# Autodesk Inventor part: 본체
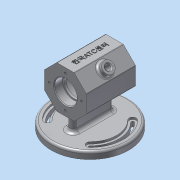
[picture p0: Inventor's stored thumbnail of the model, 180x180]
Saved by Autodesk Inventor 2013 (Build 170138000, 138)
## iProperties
Created: 2017-06
Part Number: 본체
Material: 알루미늄 6061
Document SubType Name: Modeling
Designer: Administrator
Density: 2.71 g/cm^3
Mass: 559.99 g
Surface Area: 567.595 cm^2
Volume: 206.638 cm^3
Author: Administrator
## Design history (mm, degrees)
sketch "스케치1"
  geometry: C1 r 55 at (0, 0); 1 further point
  constraints: 1 centre point, 1 coincident
  dimensions: "d0" = 110 diameter of C1
extrude "돌출1" new body sketch "스케치1" distance "d2" = 10; taper "d3" = 0 deg
sketch "스케치2"
  geometry: L1 (55, 10)-(-55, 10) reference; L2 (-55, 0)-(55, 0) reference; L3 (0, 0)-(0, 62); L4 (55, 0)-(55, 92); L5 (55, 92)-(-118.048, 92); L6 (12.426, 92)-(30, 74.426); L7 (30, 74.426)-(30, 49.574); L8 (30, 49.574)-(12.426, 32); L9 (12.426, 32)-(-12.426, 32); L10 (-12.426, 32)-(-30, 49.574); L11 (-30, 49.574)-(-30, 74.426); L12 (-30, 74.426)-(-12.426, 92); L13 (-12.426, 92)-(12.426, 92); C1 r 30 at (0, 62)
  constraints: 22 end point, 2 horizontal alignment, 1 centre point, 1 coincident, 1 parallel, 1 perpendicular, 1 vertical
  dimensions: "d5" = 60 diameter of C1; "d6" = 92 distance of L2.end L4.end; "d9" = 62 distance from line of L2 L3.end
extrude "돌출2" join sketch "스케치2" stored distance "d11" = 70; taper "d12" = 0 deg
sketch "스케치3"
  geometry: L1 (-12.426, 92)-(-30, 74.426) reference; L2 (-30, 74.426)-(-30, 49.574) reference; L3 (-30, 49.574)-(-12.426, 32) reference; L4 (-12.426, 32)-(12.426, 32) reference; L5 (12.426, 32)-(30, 49.574) reference; L6 (30, 49.574)-(30, 74.426) reference; L7 (30, 74.426)-(12.426, 92) reference; L8 (12.426, 92)-(-12.426, 92) reference; L9 (0, 0)-(0, 62); C1 r 14 at (0, 62)
  constraints: 2 end point, 1 centre point, 1 coincident, 1 perpendicular
  dimensions: "d13" = 62 distance of L9.start L9.end; "d14" = 28 diameter of C1
extrude "돌출3" cut sketch "스케치3" stored distance "d15" = 70; taper "d16" = 0 deg
sketch "스케치4"
  geometry: C1 r 14 at (0, 62) reference; C2 r 16 at (0, 62); 1 further point
  constraints: 1 centre point, 1 coincident
  dimensions: "d17" = 32 diameter of C2
extrude "돌출4" cut sketch "스케치4" distance "d19" = 12; taper "d20" = 0 deg
sketch "스케치5"
  geometry: C1 r 14 at (0, -62) reference; C2 r 16 at (0, -62); 1 further point
  constraints: 1 centre point, 1 coincident
  dimensions: "d21" = 32 diameter of C2
extrude "돌출5" cut sketch "스케치5" distance "d23" = 12; taper "d24" = 0 deg
node "작업 평면1"
sketch "스케치6"
  geometry: L1 (-30, 74.426)-(-12.426, 92) reference; L2 (-12.426, 92)-(12.426, 92) reference; L3 (12.426, 92)-(30, 74.426) reference; L4 (30, 74.426)-(30, 49.574) reference; L5 (30, 49.574)-(12.426, 32) reference; L6 (12.426, 32)-(-12.426, 32) reference; L7 (-12.426, 32)-(-30, 49.574) reference; L8 (-30, 49.574)-(-30, 74.426) reference; C1 r 16 at (0, 62) reference; C2 r 25 at (0, 62); 1 further point
  constraints: 1 centre point, 1 coincident
  dimensions: "d25" = 50 diameter of C2
extrude "돌출6" cut sketch "스케치6" stored distance "d27" = 40; taper "d28" = 0 deg
fillet "모깎기1" dims "d29" = 3
chamfer "모따기1" distance "d30" = 1; stored, may be unused: second distance "d31" = 2, angle "d32" = 45 deg
sketch "스케치7"
  geometry: L1 (0, 0)-(-78.073, 0); L2 (0, 0)-(-61.063, 61.063); L3 (0, 0)-(-59.918, -59.918); L4 (0, 0)-(76.949, 76.949); L5 (0, 0)-(92.167, 0); L6 (0, 0)-(54.196, -54.196); C1 r 55 at (0, 0) reference; A1 r 5 centre (-30.406, -30.406) between (-26.87, -26.87) and (-26.67, -33.73); A2 r 5 centre (-30.406, 30.406) between (-26.87, 26.87) and (-26.67, 33.73); A3 r 5 centre (30.406, 30.406) between (26.87, 26.87) and (26.67, 33.73); A4 r 5 centre (30.406, -30.406) between (26.87, -26.87) and (26.67, -33.73); A5 r 38 centre (0, 0) between (-26.87, 26.87) and (-26.87, -26.87); A6 r 38 centre (0, 0) between (26.87, -26.87) and (26.87, 26.87); A7 r 43 centre (0, 0) between (-26.67, 33.73) and (-26.67, -33.73); A8 r 43 centre (0, 0) between (26.67, -33.73) and (26.67, 33.73); A9 r 48 centre (0, 0) between (-33.941, 33.941) and (-33.941, -33.941); A10 r 48 centre (0, 0) between (33.941, -33.941) and (33.941, 33.941)
  constraints: 28 point on circle, 12 end point, 10 centre point, 4 point on line, 3 equal radius, 1 coincident, 1 collinear, 1 horizontal
  dimensions: "d45" = 45 deg angle of L2 L1; "d46" = 45 deg angle of L3 L1; "d47" = 45 deg angle of L4 L5; "d48" = 45 deg angle of L6 L5; "d49" = 10 diameter of A2
extrude "돌출7" cut sketch "스케치7" distance "d51" = 3; taper "d52" = 0 deg
sketch "스케치8"
  geometry: A1 r 5 centre (-30.406, 30.406) between (-26.87, 26.87) and (-33.941, 33.941) reference; A2 r 5 centre (-30.406, -30.406) between (-33.941, -33.941) and (-26.87, -26.87) reference; A3 r 5 centre (30.406, -30.406) between (26.87, -26.87) and (33.941, -33.941) reference; A4 r 48 centre (0, 0) between (33.941, -33.941) and (33.941, 33.941) reference; A5 r 5 centre (30.406, 30.406) between (33.941, 33.941) and (26.87, 26.87) reference; A6 r 38 centre (0, 0) between (26.87, -26.87) and (26.87, 26.87) reference; A7 r 2 centre (-30.406, 30.406) between (-28.991, 28.991) and (-31.82, 31.82); A8 r 2 centre (-30.406, -30.406) between (-31.82, -31.82) and (-28.991, -28.991); A9 r 2 centre (30.406, -30.406) between (28.991, -28.991) and (31.82, -31.82); A10 r 2 centre (30.406, 30.406) between (31.82, 31.82) and (28.991, 28.991); A11 r 41 centre (0, 0) between (-28.991, 28.991) and (-28.991, -28.991); A12 r 41 centre (0, 0) between (28.991, -28.991) and (28.991, 28.991); A13 r 45 centre (0, 0) between (-31.82, 31.82) and (-31.82, -31.82); A14 r 45 centre (0, 0) between (31.82, -31.82) and (31.82, 31.82)
  constraints: 16 point on circle, 8 centre point, 6 coincident, 4 tangent, 3 equal radius
  dimensions: "d53" = 4 diameter of A7
extrude "돌출8" cut sketch "스케치8" stored distance "d55" = 3; taper "d56" = 0 deg
sketch "스케치9" dims "d57" = 46
  geometry: L1 (12.426, 92)-(-12.426, 92) reference; L2 (0, 62)-(0, 85); C1 r 17 at (0, 62) reference; 2 further points
  constraints: 2 coincident, 2 end point, 1 perpendicular, 1 vertical alignment, 2 other
hole "구멍1" sketch "스케치9" at (0, 85) diameter "d59" = 3.242; stored, may be unused: countersink angle "d63" = 90 deg, drill point angle "d65" = 118 deg; dims "d60" = 8, "d61" = 4, "d62" = 2, "d64" = 10
sketch "스케치10" dims "d69" = 46
  geometry: L1 (-30, -49.574)-(-30, -74.426) reference; L2 (0, -62)-(0, -85); C1 r 17 at (0, -62) reference; 2 further points
  constraints: 2 coincident, 2 end point, 1 parallel, 1 vertical alignment, 2 other
hole "구멍2" sketch "스케치10" at (0, -85) diameter "d71" = 3.242; stored, may be unused: countersink angle "d75" = 90 deg, drill point angle "d77" = 118 deg; dims "d72" = 8, "d73" = 4, "d74" = 2, "d76" = 10
fillet "모깎기2" dims "d81" = 0.3
fillet "모깎기3" dims "d82" = 1
fillet "모깎기4" dims "d83" = 1
sketch "스케치11"
  geometry: L1 (0, 0)-(-24.024, 0) reference; C1 r 8 at (-12.012, 35); 2 further points
  constraints: 1 centre point, 1 midpoint, 1 vertical alignment
  dimensions: "d84" = 35 distance from line of L1 C1.centre; "d85" = 16 diameter of C1
extrude "돌출9" join sketch "스케치11" distance "d86" = 7; taper "d87" = 0 deg
fillet "모깎기5" dims "d88" = 3
sketch "스케치12"
  geometry: C1 r 8 at (0, 0) reference; C2 r 4 at (0, 0); 1 further point
  constraints: 1 centre point, 1 coincident
  dimensions: "d89" = 8 diameter of C2
extrude "돌출10" cut sketch "스케치12" distance "d91" = 27.5; taper "d92" = 0 deg
chamfer "모따기2" distance "d93" = 1; stored, may be unused: second distance "d94" = 2, angle "d95" = 45 deg
sketch "스케치13"
  geometry: L1 (24.024, 0)-(0, 0) reference; L2 (9.902, 9.666)-(9.902, 60.334); L3 (9.902, 60.334)-(14.708, 60.334); L4 (14.708, 60.334)-(14.708, 9.666); L5 (14.708, 9.666)-(9.902, 9.666); L6 (12.305, 9.666)-(12.305, 60.334); L7 (14.708, 35)-(9.902, 35); L8 (-17.695, 0)-(-17.695, 70) reference; 1 further point
  constraints: 4 end point, 4 midpoint, 2 other
  dimensions: "d96" = 35 distance between parallel lines of L7 L1; "d97" = 30 distance between parallel lines of L6 L8
feature "엠보싱1" sketch "스케치13" dims "d3" = 0, "d98" = 0.5, "d99" = 0
fillet "모깎기6" dims "d100" = 3
sketch "스케치14"
  geometry: L1 (0, 0)-(0, 24); L2 (0, 0)-(0, -24); L3 (-5, 24)-(-5, -24); L4 (5, 24)-(5, -24); C1 r 52 at (0, 0) reference; A1 r 5 centre (0, 24) between (5, 24) and (-5, 24); A2 r 5 centre (0, -24) between (-5, -24) and (5, -24)
  constraints: 8 end point, 4 point on circle, 3 tangent, 2 centre point, 2 coincident, 2 collinear, 1 equal radius, 1 parallel, 1 vertical
  dimensions: "d101" = 48 distance of L2.end L1.end; "d103" = 10 diameter of A1
extrude "돌출11" join sketch "스케치14" stored distance "d104" = 27.5; taper "d105" = 0 deg
fillet "모깎기8" dims "d107" = 5
node "솔리드1"
pattern_circular "원형 패턴1" dims angle "d67" = 360 deg
pattern_circular "원형 패턴2" dims angle "d79" = 360 deg
node "투영된 루프1"
node "투영된 루프2"
node "투영된 루프3"
node "투영된 루프4"
other parameters: "d33" = 96, "d35" = 76, "d38" = 86, "d41" = 96, "d43" = 76, "d44" = 86
